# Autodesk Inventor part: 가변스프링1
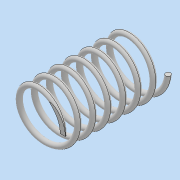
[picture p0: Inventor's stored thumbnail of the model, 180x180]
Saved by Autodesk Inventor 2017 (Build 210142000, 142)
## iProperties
Part Number: 가변스프링1
Material: 일반
Document SubType Name: Modeling
Designer: MRC
Density: 1 g/cm^3
Appearance: 기본값
Author: MRC
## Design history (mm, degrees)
sketch "스케치1"
  geometry: L1 (0, 41.411)-(10, 41.411); L2 (10, 41.411)-(10, 0); L3 (10, 0)-(0, 0); L4 (0, 0)-(0, 41.411); C1 r 1 at (10, 0); 1 further point
  constraints: 8 end point, 2 coincident, 2 parallel, 1 centre point, 1 horizontal, 1 perpendicular
  dimensions: "d0" = 41.4112 distance of L1.end L2.end (derived); "d1" = 20 diameter of L2 L4; "d2" = 2 diameter of C1
feature "코일1" sketch "스케치1" pitch "d3" = 10; turns "d5" = 7; dims "d4" = 41.4112 (= d0), "d6" = 0, angle "d7" = 90 deg, angle "d8" = 90 deg, "d9" = 0, "d10" = 0
sketch "스케치2"
  geometry: L1 (-19.444, 50)-(19.444, 50); L2 (19.444, 50)-(19.444, 0); L3 (19.444, 0)-(-19.444, 0); L4 (-19.444, 0)-(-19.444, 50); 2 further points
  constraints: 8 end point, 2 parallel, 1 coincident, 1 horizontal, 1 midpoint, 1 perpendicular
  dimensions: "d11" = 50 distance of L1.end L2.end; "d12" = 38.88889 distance of L1.start L1.end
extrude "돌출1" sketch "스케치2" stored distance "d13" = 0; taper "d14" = 0 deg
node "솔리드1"
